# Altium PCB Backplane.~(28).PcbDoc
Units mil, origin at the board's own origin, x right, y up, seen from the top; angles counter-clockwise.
Board outline 6520 x 1500 mil, 6 copper layers (Top Layer, DGND, +5V, AGND, VCC, Bottom Layer), stack 50.76 mil thick; 22 components, 84 nets, 237 pads, 4 vias.
Unrouted connection lines stored in the file: 1.
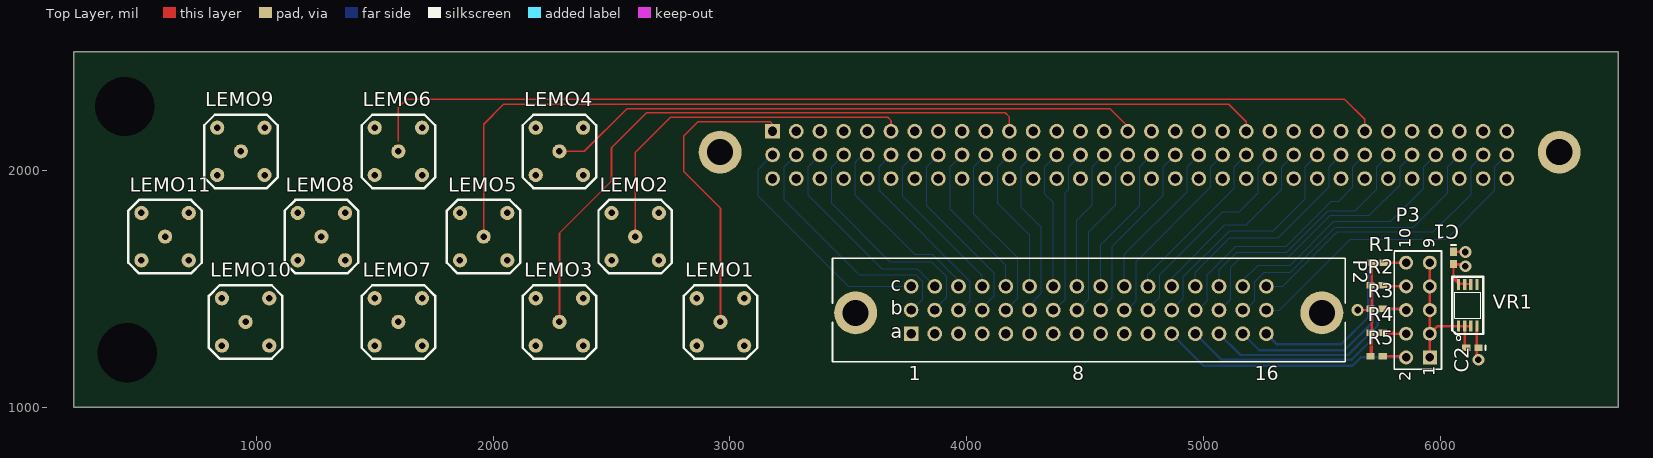
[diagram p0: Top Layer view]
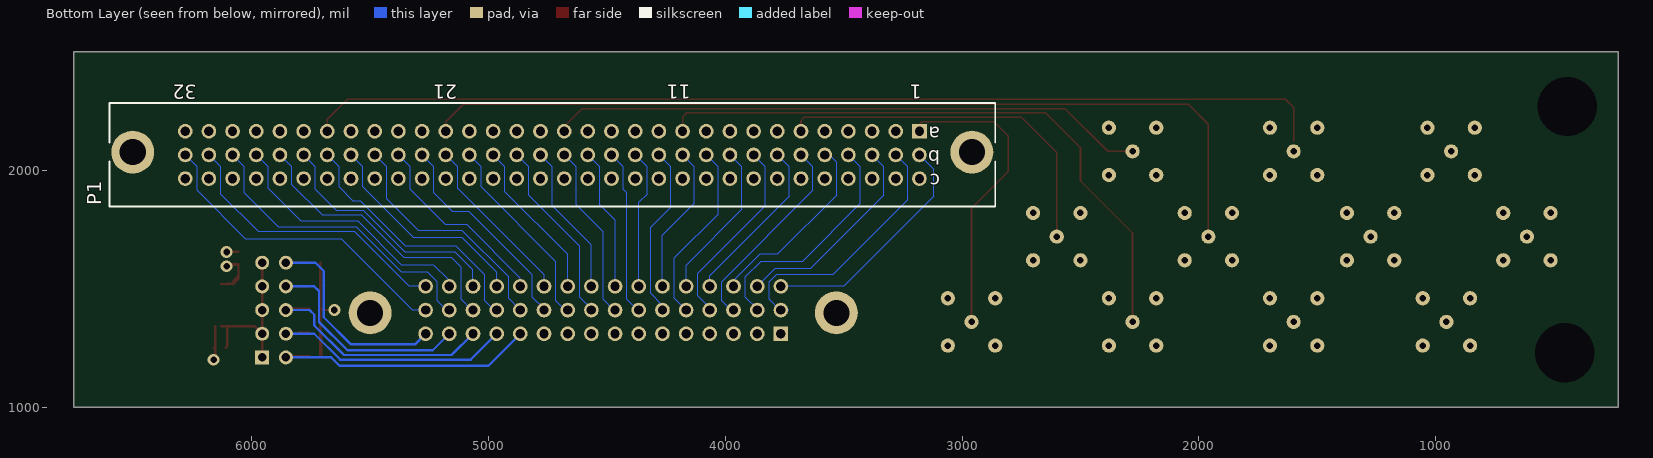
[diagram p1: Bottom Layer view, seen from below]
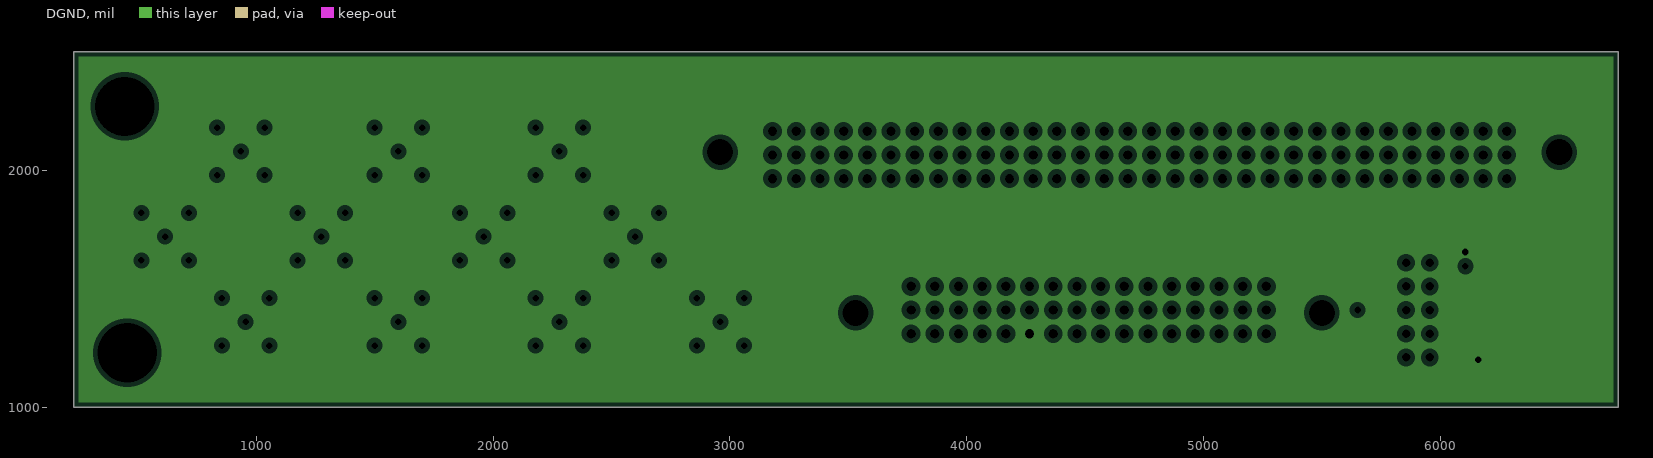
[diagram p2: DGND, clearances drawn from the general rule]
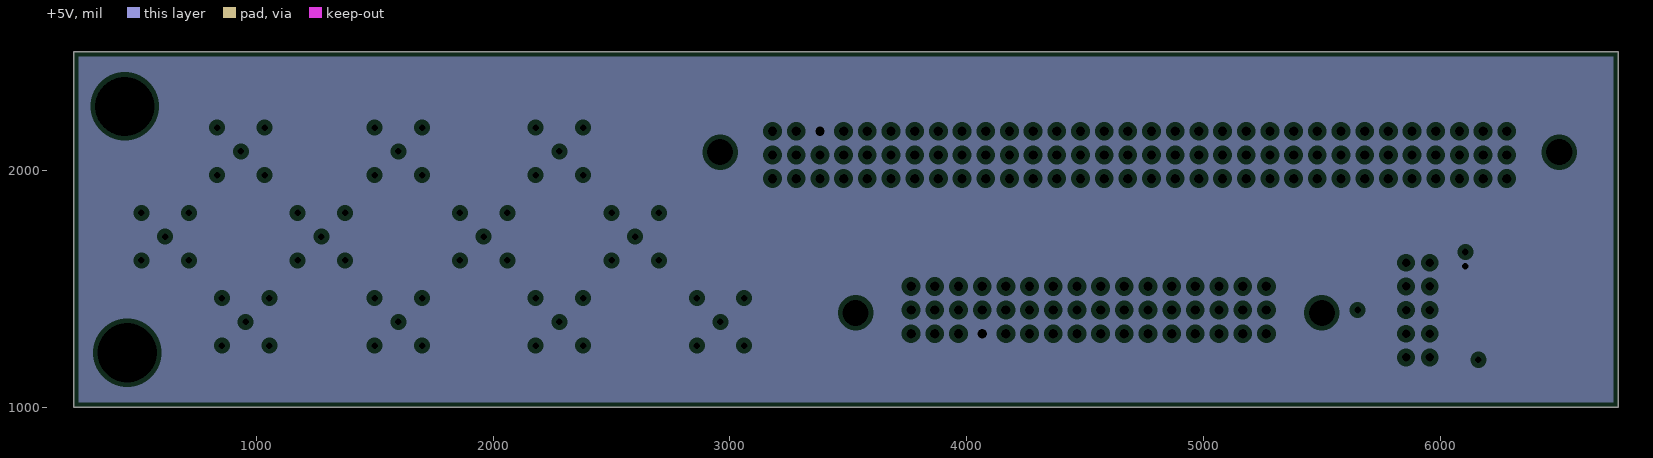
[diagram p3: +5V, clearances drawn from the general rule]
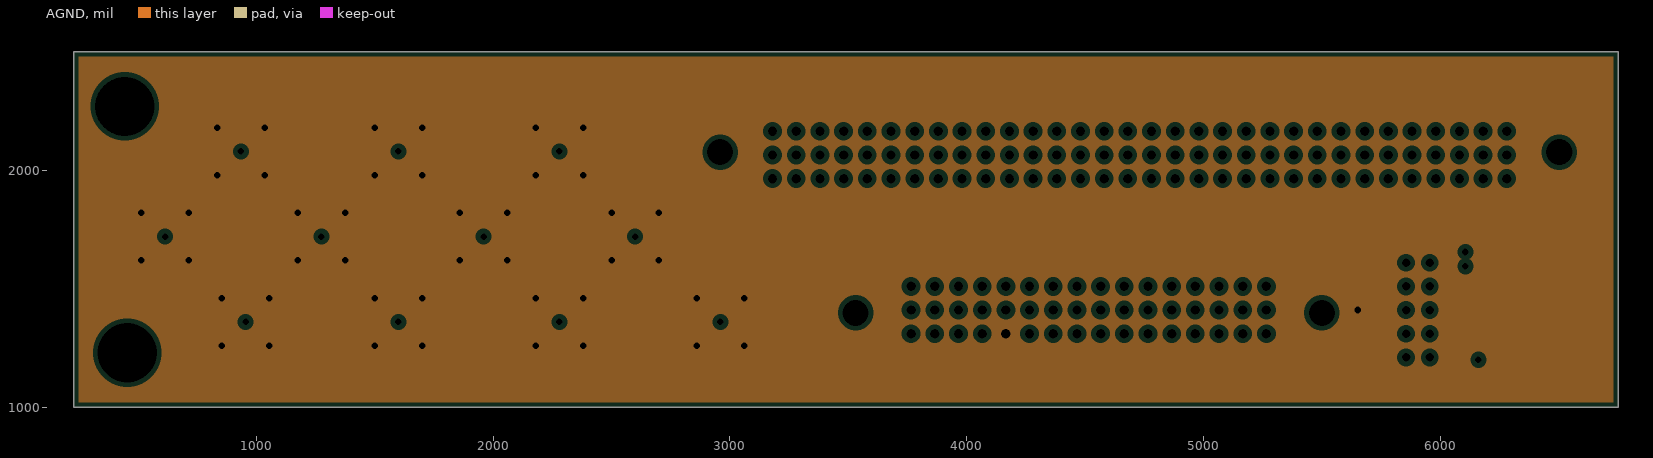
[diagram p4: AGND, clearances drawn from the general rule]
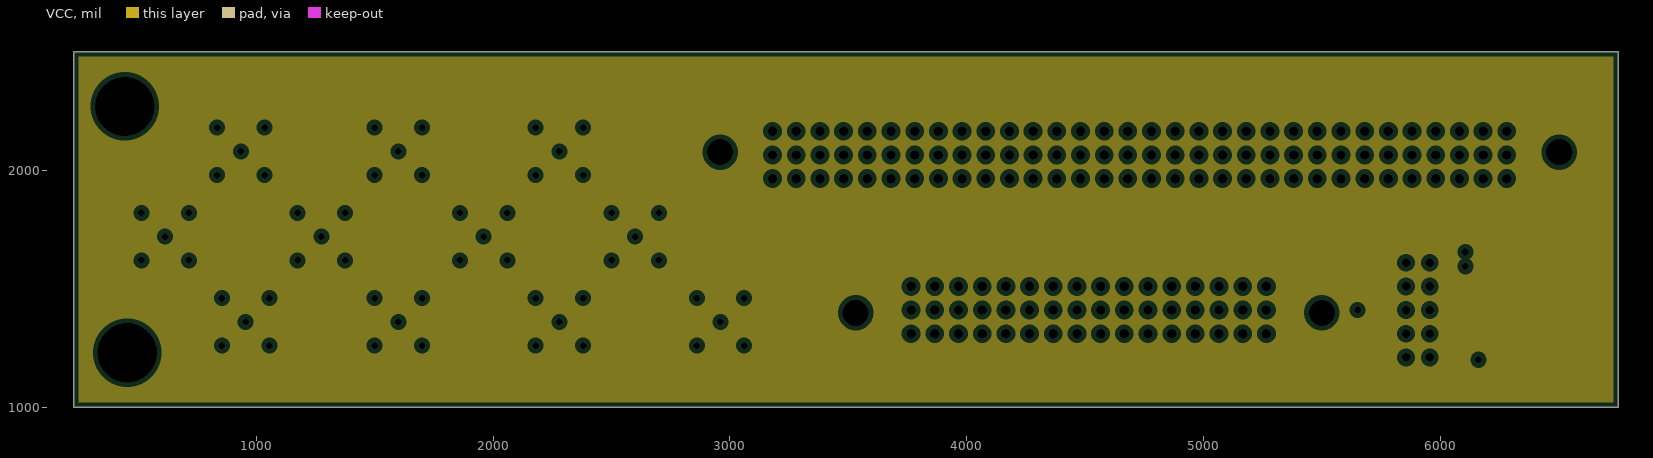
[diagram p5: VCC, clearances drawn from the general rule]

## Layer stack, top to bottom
Top Layer: signal copper 1.4
Dielectric: prepreg 5.1, FR-4, Dk 4.8
DGND: plane copper 1.4, net DGND
Dielectric: core 10.72, FR-4, Dk 4.8
+5V: plane copper 1.4, net +5V
Dielectric: prepreg 10.72, FR-4, Dk 4.8
AGND: plane copper 1.4, net AGND
Dielectric: core 10.72, FR-4, Dk 4.8
VCC: plane copper 1.4
Dielectric: prepreg 5.1, FR-4, Dk 4.8
Bottom Layer: signal copper 1.4

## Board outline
230,1000 6750,1000 6750,2500 230,2500

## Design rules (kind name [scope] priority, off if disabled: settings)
Clearance Clearance_BIAS [InNetClass('BIAS')] p1: gap=15
Clearance [All] p2: gap=10
ComponentClearance [All] p1: gap=10 collisioncheckmode=3 verticalgap=10
PlaneClearance [All] p1: clearance=20
PlaneConnect [All] p1: planeconnectstyle=Relief reliefexpansion=20 reliefentries=4 reliefconductorwidth=10 reliefairgap=10
PolygonConnect [All] p1: connectstyle=Relief reliefconductorwidth=10 reliefentries=4 polygonreliefangle="90 Angle"
RoomDefinition LEMO [InComponentClass('LEMO')] p1: confinementstyle=ConfineIn formatcopy=TRUE lockcomponents=FALSE outline 265,1030 3360,1030 3360,2385 265,2385
RoomDefinition "Digital Connector" [InComponentClass('Digital Connector')] p2: confinementstyle=ConfineIn formatcopy=TRUE lockcomponents=FALSE outline 3170,1085 6595,1085 6595,1895 3170,1895
RoomDefinition "Analog Connector" [InComponentClass('Analog Connector')] p3: confinementstyle=ConfineIn formatcopy=TRUE lockcomponents=FALSE outline 2650,1745 6670,1745 6670,2420 2650,2420
RoutingVias [All] p1: holewidth=28 width=50 viastyle="Through Hole" minholewidth=28 minwidth=50 maxholewidth=28 maxwidth=50
SolderMaskExpansion [All] p1: expansion=4
SupplyNets VCC [OnLayer('VCC')] p1: voltage=10.00
SupplyNets +5V [OnLayer('+5V')] p2: voltage=5.000
SupplyNets DGND [OnLayer(DGND)] p3: voltage=0.000
SupplyNets AGND [OnLayer('AGND')] p4: voltage=0.000
TestPointUsage [All] p1: valid=0 allowmultiple=FALSE
Testpoint [All] p1: side=15 testpointundercomponent=TRUE minsize=40 maxsize=100 preferedsize=60 minholesize=0 maxholesize=40 preferedholesize=32 testpointgrid=1 style=1023 order=0123456789
Width [All] p1: maxlimit=10 minlimit=5 preferedwidth=7
Width Width_BIAS [InNetClass('BIAS')] p2: maxlimit=10 minlimit=4 preferedwidth=5
Width Width_SIPMOUT [InNetClass('SIPMOUT')] p3: maxlimit=7.35 minlimit=2.1 preferedwidth=7.35 impedancedriven=TRUE minimp=50.000000 maximp=80.000000 favimp=50.000000
16 further rules are at their usual default settings.

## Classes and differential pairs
net class SIPMOUT: SIPMOUT1 SIPMOUT2 SIPMOUT3 SIPMOUT4 SIPMOUT5 SIPMOUT6 SIPMOUT7 SIPMOUT8 SIPMOUT9 SIPMOUT10 SIPMOUT11 SIPMOUT12 SIPMOUT13 SIPMOUT14 SIPMOUT15 SIPMOUT16 SIPMOUT17 SIPMOUT18 SIPMOUT19 SIPMOUT20 SIPMOUT21 SIPMOUT22 SIPMOUT23 SIPMOUT24 SIPMOUT25 SIPMOUT26 SIPMOUT27 SIPMOUT28 SIPMOUT29 SIPMOUT30 SIPMOUT31 SIPMOUT32 SUMMED1 SUMMED2 SUMMED3 SUMMED4 SUMMED5 SUMMED6
net class BIAS: SIPMBIAS1 SIPMBIAS2 SIPMBIAS3 SIPMBIAS4 SIPMBIAS5 SIPMBIAS6 SIPMBIAS7 SIPMBIAS8 SIPMBIAS9 SIPMBIAS10 SIPMBIAS11 SIPMBIAS12 SIPMBIAS13 SIPMBIAS14 SIPMBIAS15 SIPMBIAS16 SIPMBIAS17 SIPMBIAS18 SIPMBIAS19 SIPMBIAS20 SIPMBIAS21 SIPMBIAS22 SIPMBIAS23 SIPMBIAS24 SIPMBIAS25 SIPMBIAS26 SIPMBIAS27 SIPMBIAS28 SIPMBIAS29 SIPMBIAS30 SIPMBIAS31 SIPMBIAS32
component class LEMO: LEMO1 LEMO2 LEMO3 LEMO4 LEMO5 LEMO6 LEMO7 LEMO8 LEMO9 LEMO10 LEMO11
component class "Digital Connector": C1 C2 P2 P3 R1 R2 R3 R4 R5 R? VR1
component class "Analog Connector": P1

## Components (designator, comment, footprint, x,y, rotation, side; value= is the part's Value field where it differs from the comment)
C1 "Kemet C0402C104K8PACTU" 0402 6055,1630 r270 top
C2 "Kemet C1206C106K9PACTU" 0402 6135,1250 r180 top
LEMO1 "LEMO EPA.00" "LEMO EPA.00" 2960,1360 r0 top
LEMO2 "LEMO EPA.00" "LEMO EPA.00" 2600,1720 r0 top
LEMO3 "LEMO EPA.00" "LEMO EPA.00" 2280,1360 r0 top
LEMO4 "LEMO EPA.00" "LEMO EPA.00" 2280,2080 r0 top
LEMO5 "LEMO EPA.00" "LEMO EPA.00" 1960,1720 r0 top
LEMO6 "LEMO EPA.00" "LEMO EPA.00" 1600,2080 r0 top
LEMO7 "LEMO EPA.00" "LEMO EPA.00" 1600,1360 r0 top
LEMO8 "LEMO EPA.00" "LEMO EPA.00" 1275,1720 r0 top
LEMO9 "LEMO EPA.00" "LEMO EPA.00" 935,2080 r0 top
LEMO10 "LEMO EPA.00" "LEMO EPA.00" 955,1360 r0 top
LEMO11 "LEMO EPA.00" "LEMO EPA.00" 615,1720 r0 top
P1 "DIN41612 96 pin, Backplane" EURO2.54-2V96 4730,2065 r0 bottom
P2 "DIN41612 48 pin, Backplane" EURO2.54-2V48 4515,1410 r0 top
P3 "Header 5X2" HDR2X5 5955,1210 r90 top
R1 "Res2" 1005[0402] 5735,1610 r0 top
R2 "Res2" 1005[0402] 5730,1515 r0 top
R3 "Res2" 1005[0402] 5730,1415 r0 top
R4 "Res2" 1005[0402] 5730,1315 r0 top
R5 "Res2" 1005[0402] 5730,1215 r0 top
VR1 "" RM-8 6115,1430 r0 top

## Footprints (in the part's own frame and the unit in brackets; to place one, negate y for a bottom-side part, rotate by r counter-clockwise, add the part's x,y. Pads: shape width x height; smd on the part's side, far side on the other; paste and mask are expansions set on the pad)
0402 [mm] "Chip Capacitor; Body 1.0 x 0.5 mm (LxW typ)"
  rect 0.9x0.7 smd: 1(-0.65,0) 2(0.65,0)
  silkscreen extent -1.4,-0.25 -1.4,0.25
1005[0402] [mm] "Chip Resistor; Body 1.1 x 0.5 mm (LxW typ)"
  rect 0.9x0.7 smd: 1(-0.65,0) 2(0.65,0)
EURO2.54-2V48 [mil] "Connector; DIN 41612, Type 2C, Thru-Hole; Rows a+b+c, 48 Position; Vertical"
  round 181.1 hole 110.24: 17(-984.25,-11.81) 18(984.25,-11.81)
  rect 62x62 hole 39.37: A1(-750,-100)
  round 62 hole 39.37: A2(-650,-100) A3(-550,-100) A4(-450,-100) A5(-350,-100) A6(-250,-100) A7(-150,-100) A8(-50,-100) A9(50,-100) A10(150,-100) A11(250,-100) A12(350,-100) A13(450,-100) A14(550,-100) A15(650,-100) A16(750,-100) B1(-750,0) B2(-650,0) B3(-550,0) B4(-450,0) B5(-350,0) B6(-250,0) B7(-150,0) B8(-50,0) B9(50,0) B10(150,0) B11(250,0) B12(350,0) B13(450,0) B14(550,0) B15(650,0) B16(750,0) C1(-750,100) C2(-650,100) C3(-550,100) C4(-450,100) C5(-350,100) C6(-250,100) C7(-150,100) C8(-50,100) C9(50,100) C10(150,100) C11(250,100) C12(350,100) C13(450,100) C14(550,100) C15(650,100) C16(750,100)
  silkscreen extent -1083,-219 1083,219
EURO2.54-2V96 [mil] "Connector; DIN 41612, Type C, Thru-Hole; Rows a+b+c, 96 Position; Vertical"
  round 181.1 hole 110.24: 33(-1771.65,-11.81) 34(1771.65,-11.81)
  rect 62x62 hole 39.37: A1(-1550,-100)
  round 62 hole 39.37: A2(-1450,-100) A3(-1350,-100) A4(-1250,-100) A5(-1150,-100) A6(-1050,-100) A7(-950,-100) A8(-850,-100) A9(-750,-100) A10(-650,-100) A11(-550,-100) A12(-450,-100) A13(-350,-100) A14(-250,-100) A15(-150,-100) A16(-50,-100) A17(50,-100) A18(150,-100) A19(250,-100) A20(350,-100) A21(450,-100) A22(550,-100) A23(650,-100) A24(750,-100) A25(850,-100) A26(950,-100) A27(1050,-100) A28(1150,-100) A29(1250,-100) A30(1350,-100) A31(1450,-100) A32(1550,-100) B1(-1550,0) B2(-1450,0) B3(-1350,0) B4(-1250,0) B5(-1150,0) B6(-1050,0) B7(-950,0) B8(-850,0) B9(-750,0) B10(-650,0) B11(-550,0) B12(-450,0) B13(-350,0) B14(-250,0) B15(-150,0) B16(-50,0) B17(50,0) B18(150,0) B19(250,0) B20(350,0) B21(450,0) B22(550,0) B23(650,0) B24(750,0) B25(850,0) B26(950,0) B27(1050,0) B28(1150,0) B29(1250,0) B30(1350,0) B31(1450,0) B32(1550,0) C1(-1550,100) C2(-1450,100) C3(-1350,100) C4(-1250,100) C5(-1150,100) C6(-1050,100) C7(-950,100) C8(-850,100) C9(-750,100) C10(-650,100) C11(-550,100) C12(-450,100) C13(-350,100) C14(-250,100) C15(-150,100) C16(-50,100) C17(50,100) C18(150,100) C19(250,100) C20(350,100) C21(450,100) C22(550,100) C23(650,100) C24(750,100) C25(850,100) C26(950,100) C27(1050,100) C28(1150,100) C29(1250,100) C30(1350,100) C31(1450,100) C32(1550,100)
  silkscreen extent -1870,-219 1870,219
HDR2X5 [mm] "Connector; Header; 5x2 Position"
  rect 1.5x1.5 hole 0.9: 1(0,0)
  round 1.5 hole 0.9: 2(0,2.54) 3(2.54,0) 4(2.54,2.54) 5(5.08,0) 6(5.08,2.54) 7(7.62,0) 8(7.62,2.54) 9(10.16,0) 10(10.16,2.54)
  silkscreen extent -1.27,-1.27 11.43,3.81
"LEMO EPA.00" [mil]
  round 60 hole 27.56: 0(0,0) 1(-100,100) 2(100,100) 3(100,-100) 4(-100,-100)
  silkscreen extent -155,-155 155,155
RM-8 [mil]
  rect 13.4x46.9 smd: 1(-38.6,-87.8) 2(-12.6,-87.8) 3(12.6,-87.8) 4(38.6,-87.8) 5(38.6,87.8) 6(12.6,87.8) 7(-12.6,87.8) 8(-38.6,87.8)
  silkscreen extent -65,-148 65,121

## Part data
C1 C2: library part Cap, "Capacitor"
P3: "Header, 5-Pin, Dual row"
R1 R2 R3 R4 R5: "Resistor"
VR1: library part ADP3335

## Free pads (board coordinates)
  round 60 hole 250: 0(445,2270) 0(455,1230)

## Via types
v1: diameter 50, hole 28, Top Layer to Bottom Layer, 4 vias

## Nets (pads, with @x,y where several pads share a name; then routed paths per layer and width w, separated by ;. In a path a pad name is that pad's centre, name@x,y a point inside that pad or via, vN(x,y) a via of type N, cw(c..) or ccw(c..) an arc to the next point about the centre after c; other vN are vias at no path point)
+3.3V: C2.2 P3.1 P3.3 P3.5 P3.7 P3.9 VR1.1 VR1.2 VR1.3 | length 681
  Top Layer w10: P3.1 P3.3 ; P3.9 P3.7 P3.5 P3.3 ; C2.2 6102.4,1257.01 VR1.2 ; VR1.3 VR1.2 ; P3.3 5987.2,1342.2 VR1.1 VR1.2
+5V: C1.2 P1.A3 P2.A4 VR1.6 VR1.7 VR1.8 | length 470.4
  Top Layer w10: VR1.8 VR1.8@6076.4,1521 ; VR1.7 VR1.7@6102.4,1520 ; v1(6105,1595) v1@6100,1600 ; VR1.6 VR1.6@6127.6,1520 ; 6055,1554.4 C1.2@6055,1600 ; 6055,1554.4 6055,1543.6 VR1.8@6076.4,1522.2 ; 6055,1554.4 6076.4,1533 VR1.8@6076.4,1522.2 ; C1.2@6055,1600 v1@6100,1600 ; C1.2@6055,1600 C1.2 6095.59,1604.41 v1@6100,1600 ; C1.2@6055,1600 v1@6100,1600 ; VR1.8@6076.4,1521 VR1.8@6077.6,1521 ; VR1.8@6076.4,1521 VR1.8@6076.4,1522.2 ; VR1.8@6076.4,1521 VR1.8@6077.6,1521 ; VR1.8@6076.4,1522.2 VR1.8@6077.6,1521 ; VR1.8@6077.6,1521 VR1.8@6078.6,1520 ; VR1.8@6077.6,1521 VR1.7@6102.4,1521 ; VR1.8@6077.6,1521 VR1.7@6102.4,1521 ; VR1.8@6077.6,1521 VR1.8@6078.6,1520 ; VR1.8@6078.6,1520 VR1.7@6102.4,1520 ; VR1.8@6078.6,1520 VR1.7@6102.4,1520 ; v1@6100,1600 v1@6105,1600 ; v1@6100,1600 v1@6105,1600 ; VR1.7@6102.4,1520 VR1.6@6127.6,1520 ; VR1.7@6102.4,1520 VR1.7@6102.4,1521 ; VR1.7@6102.4,1520 VR1.6@6127.6,1520 ; v1@6105,1600 6115,1600 v1@6105,1600
+210V: P2.A2
-5V: P2.A3
ADC_EXT1: P2.A7
ADC_EXT2: P2.A8
AGND: LEMO1.1 LEMO1.2 LEMO1.3 LEMO1.4 LEMO2.1 LEMO2.2 LEMO2.3 LEMO2.4 LEMO3.1 LEMO3.2 LEMO3.3 LEMO3.4 LEMO4.1 LEMO4.2 LEMO4.3 LEMO4.4 LEMO5.1 LEMO5.2 LEMO5.3 LEMO5.4 LEMO6.1 LEMO6.2 LEMO6.3 LEMO6.4 LEMO7.1 LEMO7.2 LEMO7.3 LEMO7.4 LEMO8.1 LEMO8.2 LEMO8.3 LEMO8.4 LEMO9.1 LEMO9.2 LEMO9.3 LEMO9.4 LEMO10.1 LEMO10.2 LEMO10.3 LEMO10.4 LEMO11.1 LEMO11.2 LEMO11.3 LEMO11.4 P2.A5 R1.1 R2.1 R3.1 R4.1 R5.1 | length 1259.6
  Top Layer w10: v1(5650,1410) R3.1@5699.41,1410 ; R5.1 R5.1@5705,1215 ; R4.1 R4.1@5705,1315 ; R2.1 R2.1@5709,1515 ; R3.1@5699.41,1410 R3.1@5699.41,1415 ; R3.1@5699.41,1410 R3.1@5699.41,1415 ; R3.1@5699.41,1415 R3.1 R3.1@5709,1415 ; R5.1@5705,1215 R4.1@5705,1315 ; R5.1@5705,1215 R4.1@5705,1315 ; R4.1@5705,1315 R4.1@5709.41,1315 ; R3.1@5709,1415 R2.1@5709,1515 ; R3.1@5709,1415 R2.1@5709,1515 ; R2.1@5709,1515 R2.1@5709.41,1515 ; R4.1@5709.41,1315 5709.41,1220 R4.1@5709.41,1315 ; R4.1@5709.41,1315 R3.1@5709.41,1415 ; R4.1@5709.41,1315 R3.1@5709.41,1415 ; R3.1@5709.41,1415 R2.1@5709.41,1515 ; R3.1@5709.41,1415 R2.1@5709.41,1515 ; R2.1@5709.41,1515 R1.1 R2.1@5709.41,1515
CP2201/LA: P2.A1
DGND: C1.1 C2.1 P2.A6 VR1.4 | length 337.9
  Top Layer w10: C1.1 6104.41,1655.59 v1(6105,1655) ; v1(6160,1200) v1@6153.6,1206.4 ; C2.1 C2.1@6153.6,1250 ; v1@6153.6,1206.4 C2.1@6153.6,1250 ; v1@6153.6,1206.4 C2.1@6153.6,1250 ; C2.1@6153.6,1250 VR1.4 C2.1@6153.6,1250
ID0: P2.A16 P3.10 R1.2 | length 960.2
  Top Layer w10: R1.2 P3.10
  Bottom Layer w10: P2.A16 5310,1265 5580,1265 5695,1380 5695,1575 5730,1610 P3.10
ID1: P2.A15 P3.8 R2.2 | length 1001.4
  Top Layer w10: R2.2@5760.59,1510 P3.8
  Bottom Layer w10: P2.A15 5235,1240 5595,1240 5715,1360 5715,1490 5735,1510 P3.8
ID2: P2.A14 P3.6 R3.2 | length 1136.2
  Top Layer w10: P3.6 P3.6@5855,1415 ; P3.6@5855,1415 R3.2 P3.6@5855,1415
  Bottom Layer w10: P2.A14 5155,1220 5610,1220 5735,1345 5735,1390 5755,1410 P3.6
ID3: P2.A13 P3.4 R4.2 | length 1129
  Top Layer w10: R4.2 5802,1315 5807,1310 ; R4.2@5760.59,1310 5807,1310 ; P3.4 5807,1310
  Bottom Layer w10: P2.A13 5075,1200 5625,1200 5735,1310 P3.4
ID4: P2.A12 P3.2 R5.2 | length 1264.2
  Top Layer w10: P3.2 P3.2@5855,1215 ; P3.2@5855,1215 R5.2 P3.2@5855,1215
  Bottom Layer w10: P2.A12 5000,1175 5628.28,1175 5663.28,1210 P3.2
SIPMBIAS1: P1.B1 P2.C1 | length 1002.3
  Bottom Layer w5: P1.B1 3120,2005 3120,1890 3500,1510 P2.C1
SIPMBIAS2: P1.B2 P2.B1 | length 1117.3
  Bottom Layer w5: P1.B2 3230,2015 3230,1875 3545,1560 3785,1560 3815,1530 3815,1455 3770,1410 P2.B1 P2.B1@3765,1415
  Bottom Layer w10: P2.B1@3735,1410 P2.B1
SIPMBIAS3: P1.B3 P2.C2 | length 885.2
  Bottom Layer w5: P1.B3 3330,2015 3330,1895 3640,1585 3790,1585 P2.C2
SIPMBIAS4: P1.B4 P2.B2 | length 999.8
  Bottom Layer w5: P1.B4 3430,2015 3430,1860 3675,1615 3850,1615 3915,1550 3915,1465 3865,1415 P2.B2
SIPMBIAS5: P1.B5 P2.C3 | length 811.5
  Bottom Layer w5: P1.B5 3560,2065 3530,2035 3530,1895 3780,1645 3855,1645 3965,1535 P2.C3
SIPMBIAS6: P1.B6 P2.B3 | length 861.8
  Bottom Layer w5: P1.B6 3630,2015 3630,1915 4015,1530 4015,1450 3975,1410 P2.B3
SIPMBIAS7: P1.B7 P2.C4 | length 714.5
  Bottom Layer w5: P1.B7 3730,2015 3730,1890 4065,1555 P2.C4
SIPMBIAS8: P1.B8 P2.B4 | length 814.5
  Bottom Layer w5: P1.B8 3830,2015 3830,1850 4115,1565 4115,1470 4065,1420 P2.B4
SIPMBIAS9: P1.B9 P2.C5 | length 673.1
  Bottom Layer w5: P1.B9 3930,2015 3930,1835 4165,1600 P2.C5
SIPMBIAS10: P1.B10 P2.B5 | length 773.1
  Bottom Layer w5: P1.B10 4030,2015 4030,1815 4215,1630 4215,1460 P2.B5
SIPMBIAS11: P1.B11 P2.C6 | length 631.6
  Bottom Layer w5: P1.B11 4130,2015 4130,1860 4265,1725 P2.C6
SIPMBIAS12: P1.B12 P2.B6 | length 731.6
  Bottom Layer w5: P2.B6 4265,1430 4315,1480 4315,1760 4230,1845 4230,2015 P1.B12
SIPMBIAS13: P1.B13 P2.C7 | length 590.2
  Bottom Layer w5: P2.C7 4365,1865 4330,1900 4330,2015 P1.B13
SIPMBIAS14: P1.B14 P2.B7 | length 705.6
  Bottom Layer w5: P2.B7 4370,1410 4415,1455 4415,1905 4430,1920 4430,2015 P1.B14
SIPMBIAS15: P1.B15 P2.C8 | length 602.6
  Bottom Layer w5: P2.C8 4465,1790 4530,1855 4530,2015 P1.B15
SIPMBIAS16: P1.B16 P2.B8 | length 747
  Bottom Layer w5: P2.B8 4470,1410 4515,1455 4515,1740 4630,1855 4630,2015 P1.B16
SIPMBIAS17: P1.B17 P2.C9 | length 644.1
  Bottom Layer w5: P2.C9 4565,1685 4730,1850 4730,2015 P1.B17
SIPMBIAS18: P1.B18 P2.B9 | length 785.5
  Bottom Layer w5: P2.B9 4565,1415 4615,1465 4615,1680 4830,1895 4830,2015 P1.B18
SIPMBIAS19: P1.B19 P2.C10 | length 685.5
  Bottom Layer w5: P2.C10 4665,1645 4930,1910 4930,2015 P1.B19
SIPMBIAS20: P1.B20 P2.B10 | length 832.8
  Bottom Layer w5: P2.B10 4675,1410 4715,1450 4715,1615 5030,1930 5030,2015 P1.B20
SIPMBIAS21: P1.B21 P2.C11 | length 726.9
  Bottom Layer w5: P2.C11 4765,1560 5130,1925 5130,2015 P1.B21
SIPMBIAS22: P1.B22 P2.B11 | length 909.3
  Bottom Layer w5: P2.B11 4765,1415 4815,1465 4815,1560 5080,1825 5150,1825 5230,1905 5230,2015 P1.B22
SIPMBIAS23: P1.B23 P2.C12 | length 821
  Bottom Layer w5: P2.C12 4865,1545 5090,1770 5180,1770 5330,1920 5330,2015 P1.B23
SIPMBIAS24: P1.B24 P2.B12 | length 1018.1
  Bottom Layer w5: P2.B12 4915,1460 4915,1550 5110,1745 5295,1745 5430,1880 5430,2015 P1.B24
SIPMBIAS25: P1.B25 P2.C13 | length 929.8
  Bottom Layer w5: P2.C13 4965,1570 5110,1715 5315,1715 5530,1930 5530,2015 P1.B25
SIPMBIAS26: P1.B26 P2.B13 | length 1100.5
  Bottom Layer w5: P2.B13 4975,1410 5015,1450 5015,1560 5135,1680 5348.43,1680 5538.43,1870 5570,1870 5630,1930 5630,2015 P1.B26
SIPMBIAS27: P1.B27 P2.C14 | length 1041.5
  Bottom Layer w5: P2.C14 5065,1580 5140,1655 5351.72,1655 5526.72,1830 5640,1830 5730,1920 5730,2015 P1.B27
SIPMBIAS28: P1.B28 P2.B14 | length 1209.3
  Bottom Layer w5: P2.B14 5070,1410 5115,1455 5115,1590 5155,1630 5355,1630 5535,1810 5700,1810 5830,1940 5830,2015 P1.B28
SIPMBIAS29: P1.B29 P2.C15 | length 1112.3
  Bottom Layer w5: P2.C15 5165,1535 5230,1600 5365,1600 5550,1785 5790,1785 5930,1925 5930,2015 P1.B29
SIPMBIAS30: P1.B30 P2.B15 | length 1297.6
  Bottom Layer w5: P2.B15 5175,1410 5215,1450 5215,1530 5255,1570 5365,1570 5555,1760 5885,1760 6030,1905 6030,2015 P1.B30
SIPMBIAS31: P1.B31 P2.C16 | length 1212.3
  Bottom Layer w5: P2.C16 5335,1510 5565,1740 5970,1740 6130,1900 6130,2015 P1.B31
SIPMBIAS32: P1.B32 P2.B16 | length 1344.9
  Bottom Layer w5: P2.B16 5320,1410 5620,1710 6025,1710 6230,1915 6230,2015 P1.B32
SIPMOUT1: P1.C1
SIPMOUT2: P1.C2
SIPMOUT3: P1.C3
SIPMOUT4: P1.C4
SIPMOUT5: P1.C5
SIPMOUT6: P1.C6
SIPMOUT7: P1.C7
SIPMOUT8: P1.C8
SIPMOUT9: P1.C9
SIPMOUT10: P1.C10
SIPMOUT11: P1.C11
SIPMOUT12: P1.C12
SIPMOUT13: P1.C13
SIPMOUT14: P1.C14
SIPMOUT15: P1.C15
SIPMOUT16: P1.C16
SIPMOUT17: P1.C17
SIPMOUT18: P1.C18
SIPMOUT19: P1.C19
SIPMOUT20: P1.C20
SIPMOUT21: P1.C21
SIPMOUT22: P1.C22
SIPMOUT23: P1.C23
SIPMOUT24: P1.C24
SIPMOUT25: P1.C25
SIPMOUT26: P1.C26
SIPMOUT27: P1.C27
SIPMOUT28: P1.C28
SIPMOUT29: P1.C29
SIPMOUT30: P1.C30
SIPMOUT31: P1.C31
SIPMOUT32: P1.C32
SUMMED1: LEMO1.0 LEMO6.0 P1.A1 | length 1283.2
  Top Layer w7: LEMO1.0 2960,1840 2805,1995 2805,2145 2865,2205 3170,2205 3180,2195 P1.A1
SUMMED2: LEMO2.0 P1.A6 | length 1547.3
  Top Layer w7: LEMO2.0 2600,2075 2748.75,2223.75 3666.25,2223.75 3680,2210 P1.A6
SUMMED3: LEMO3.0 P1.A11 | length 2634.5
  Top Layer w7: LEMO3.0 2280,1735 2500,1955 2500,2095 2647.5,2242.5 4162.5,2242.5 4180,2225 P1.A11
SUMMED4: LEMO4.0 P1.A16 | length 2525.6
  Top Layer w7: LEMO4.0 2385,2080 2565,2260 4605,2260 4680,2185 P1.A16
SUMMED5: LEMO5.0 P1.A21 | length 3800.2
  Top Layer w7: LEMO5.0 1960,2195 2043.75,2278.75 5106.25,2278.75 5180,2205 P1.A21
SUMMED6: P1.A26 | length 4321.2
  Top Layer w7: 1600,2123.5 1600,2265 1635,2300 5595,2300 5680,2215 P1.A26
pads on no net: LEMO7.0 LEMO8.0 LEMO9.0 LEMO10.0 LEMO11.0 P1.33 P1.34 P1.A2 P1.A4 P1.A5 P1.A7 P1.A8 P1.A9 P1.A10 P1.A12 P1.A13 P1.A14 P1.A15 P1.A17 P1.A18 P1.A19 P1.A20 P1.A22 P1.A23 P1.A24 P1.A25 P1.A27 P1.A28 P1.A29 P1.A30 P1.A31 P1.A32 P2.17 P2.18 P2.A9 P2.A10 P2.A11 VR1.5

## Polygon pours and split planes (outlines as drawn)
DGND on DGND (split plane): 6729.61,1020.39 250.39,1020.39 250.39,2479.61 6729.61,2479.61
AGND on AGND (split plane): 6729.61,1020.39 250.39,1020.39 250.39,2479.61 6729.61,2479.61
+5V on +5V (split plane): 6729.61,1020.39 250.39,1020.39 250.39,2479.61 6729.61,2479.61
no net on VCC (split plane): 6729.61,1020.39 250.39,1020.39 250.39,2479.61 6729.61,2479.61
